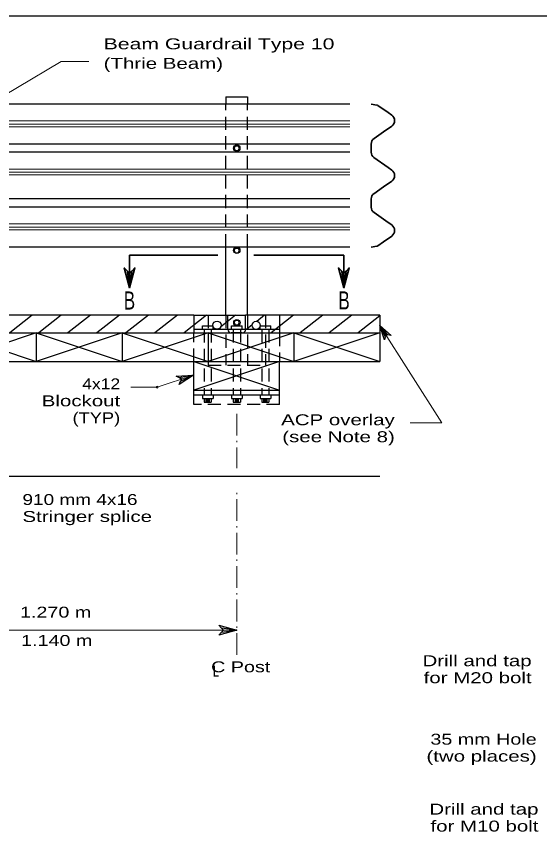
# Model space of a CAD drawing. Extents: x 13426 to 15509, y -9298 to -5111.
# Drawn here: x 15263.4 to 15326, y -5208.6 to -5111 of the extents above; entities that cross this region are included whole.
import ezdxf
from ezdxf.enums import TextEntityAlignment as Align

# ---------------------------------------------------------------- set-up
doc = ezdxf.new("R2010")
doc.units = 0
doc.header["$LTSCALE"] = 0.52
doc.header["$PDMODE"] = 32
doc.header["$PDSIZE"] = 0.26
doc.linetypes.add('DOT_DASHED', pattern=[7.7, 5, -1.2, 0.3, -1.2])
doc.linetypes.add('MEDIUM_DASHED', pattern=[4.5, 3, -1.5])
for name, color, linetype, lineweight in [('1', 7, 'Continuous', 13), ('15', 7, 'Continuous', 13), ('16', 7, 'Continuous', 25), ('2', 7, 'Continuous', 25), ('20', 7, 'Continuous', 13), ('30', 7, 'Continuous', 25), ('4', 7, 'Continuous', 13), ('5', 7, 'Continuous', 25)]:
    doc.layers.add(name, color=color, linetype=linetype, lineweight=lineweight)
doc.layers.add('19', color=7, linetype='Continuous')

msp = doc.modelspace()

# ---------------------------------------------------------------- linework, layer by layer
at = {"layer": '1', "lineweight": 25}
for p, q in [((15303.296, -5121.538), (15188.44, -5121.538)), ((15303.296, -5126.334), (15188.44, -5126.334)), ((15289.467, -5126.809), (15289.626, -5126.535)), ((15289.626, -5126.535), (15289.947, -5126.535)), ((15290.105, -5126.813), (15289.947, -5126.535)), ((15303.296, -5127.298), (15188.44, -5127.298)), ((15289.626, -5127.091), (15289.467, -5126.809)), ((15289.626, -5127.091), (15289.943, -5127.091)), ((15289.943, -5127.091), (15290.105, -5126.813)), ((15303.296, -5132.898), (15188.44, -5132.898)), ((15305.869, -5133.864), (15305.869, -5132.898)), ((15303.296, -5133.864), (15188.44, -5133.864)), ((15303.296, -5138.664), (15188.44, -5138.664)), ((15289.467, -5139.043), (15289.626, -5138.769)), ((15289.626, -5139.326), (15289.467, -5139.043)), ((15289.626, -5138.769), (15289.947, -5138.769)), ((15289.626, -5139.326), (15289.943, -5139.326)), ((15289.943, -5139.326), (15290.105, -5139.047)), ((15290.105, -5139.047), (15289.947, -5138.769)), ((15284.634, -5146.793), (15193.834, -5146.793)), ((15284.634, -5146.793), (15284.634, -5148.935)), ((15284.634, -5146.793), (15290.845, -5146.793)), ((15288.704, -5148.507), (15288.704, -5146.793)), ((15306.907, -5146.793), (15290.845, -5146.793)), ((15290.845, -5148.507), (15290.845, -5146.793)), ((15294.914, -5146.793), (15294.914, -5148.935)), ((15289.48, -5147.691), (15289.639, -5147.416)), ((15289.639, -5147.973), (15289.48, -5147.691)), ((15289.639, -5147.416), (15289.96, -5147.416)), ((15289.639, -5147.973), (15289.956, -5147.973)), ((15289.956, -5147.973), (15290.119, -5147.695)), ((15290.119, -5147.695), (15289.96, -5147.416)), ((15294.914, -5148.507), (15284.634, -5148.507)), ((15290.417, -5148.935), (15289.132, -5148.935)), ((15284.634, -5156.323), (15284.634, -5152.362)), ((15294.914, -5156.323), (15294.914, -5152.362))]:
    msp.add_line(p, q, dxfattribs=at)
at = {"layer": '1', "lineweight": 35}
for p, q in [((15305.869, -5121.538), (15306.541, -5121.657)), ((15307.879, -5122.562), (15306.672, -5121.712)), ((15308.324, -5122.867), (15307.881, -5122.56)), ((15308.324, -5124.198), (15307.35, -5124.87)), ((15307.351, -5124.87), (15306.214, -5125.671)), ((15305.869, -5127.307), (15305.869, -5126.334)), ((15307.886, -5129.129), (15306.167, -5127.94)), ((15308.324, -5129.446), (15307.881, -5129.136)), ((15307.351, -5131.443), (15306.167, -5132.27)), ((15308.324, -5130.766), (15307.352, -5131.446)), ((15305.869, -5132.898), (15305.869, -5133.864)), ((15308.324, -5137.334), (15307.351, -5138.015)), ((15307.351, -5138.013), (15306.672, -5138.495)), ((15305.871, -5138.664), (15306.543, -5138.549))]:
    msp.add_line(p, q, dxfattribs=at)
at = {"layer": '1'}
for p, q in [((15303.296, -5123.566), (15188.44, -5123.566)), ((15303.296, -5123.949), (15188.44, -5123.949)), ((15303.296, -5124.268), (15188.44, -5124.268)), ((15303.296, -5129.326), (15188.44, -5129.326)), ((15303.296, -5129.709), (15188.44, -5129.709)), ((15303.296, -5130.028), (15188.44, -5130.028)), ((15303.296, -5135.893), (15188.44, -5135.893)), ((15303.296, -5136.276), (15188.44, -5136.276)), ((15303.296, -5136.595), (15188.44, -5136.595))]:
    msp.add_line(p, q, dxfattribs=at)
at = {"layer": '1', "linetype": 'MEDIUM_DASHED', "lineweight": 25}
for p, q in [((15284.634, -5152.362), (15284.634, -5148.935)), ((15294.914, -5148.935), (15294.914, -5152.362)), ((15294.914, -5157.501), (15294.914, -5156.323))]:
    msp.add_line(p, q, dxfattribs=at)
at = {"layer": '1', "lineweight": 35}
msp.add_lwpolyline([(15308.324, -5136.012), (15307.881, -5135.705), (15306.214, -5134.537)], dxfattribs=at)
at = {"layer": '1', "linetype": 'MEDIUM_DASHED', "lineweight": 25}
msp.add_lwpolyline([(15294.914, -5157.501), (15284.634, -5157.501), (15284.634, -5156.323)], dxfattribs=at)
at = {"layer": '1', "lineweight": 25}
for centre in [(15287.4185, -5147.9974), (15292.1095, -5148.0187)]:
    msp.add_circle(centre, 0.4819, dxfattribs=at)
for centre, radius, start, end in [((15306.4821, -5121.9768), 0.3231, 55.00074, 79.99915), ((15307.8591, -5130.1024), 0.8078, 304.98394, 55.01555), ((15289.1318, -5148.5067), 0.4283, 180, 269.99999), ((15290.4167, -5148.5067), 0.4283, 270, 359.99999)]:
    msp.add_arc(centre, radius, start, end, dxfattribs=at)
at = {"layer": '1', "lineweight": 35}
for centre, radius, start, end in [((15307.8591, -5123.5327), 0.8078, 304.98447, 55.01608), ((15306.6745, -5126.3329), 0.8078, 124.98447, 180.00047), ((15306.6745, -5127.3022), 0.8078, 179.99952, 235.01552), ((15307.8591, -5130.1023), 0.8078, 304.98447, 55.01608), ((15306.6745, -5132.9025), 0.8078, 124.98453, 180.00053), ((15306.6745, -5133.8718), 0.8078, 179.99957, 235.01557), ((15307.8591, -5136.672), 0.8078, 304.98394, 55.01555), ((15306.4865, -5138.2301), 0.3231, 280.00088, 304.99929)]:
    msp.add_arc(centre, radius, start, end, dxfattribs=at)
at = {"layer": '15', "lineweight": 35}
for p, q in [((15276.957, -5139.625), (15276.957, -5143.516)), ((15276.957, -5139.625), (15287.511, -5139.625)), ((15291.823, -5139.625), (15302.595, -5139.625)), ((15302.595, -5139.625), (15302.595, -5143.516))]:
    msp.add_line(p, q, dxfattribs=at)
at = {"layer": '15'}
for p, q in [((15280.253, -5155.411), (15284.602, -5153.97)), ((15277.122, -5155.411), (15280.253, -5155.411))]:
    msp.add_line(p, q, dxfattribs=at)
for points in [[(15258.277, -5122.691), (15268.79, -5116.467), (15272.079, -5116.467)], [(15310.526, -5159.697), (15314.323, -5159.697), (15306.907, -5148.036)]]:
    msp.add_lwpolyline(points, dxfattribs=at)
msp.add_point((15280.253, -5155.411), dxfattribs=at)
at = {"layer": '16', "lineweight": 35}
for points in [[(15277.218, -5141.525), (15277.601, -5141.158), (15276.957, -5143.516), (15276.314, -5141.158), (15276.697, -5141.525), (15276.957, -5143.516), (15277.218, -5141.525), (15276.957, -5141.786), (15276.697, -5141.525)], [(15302.856, -5141.525), (15303.238, -5141.158), (15302.595, -5143.516), (15301.952, -5141.158), (15302.335, -5141.525), (15302.595, -5143.516), (15302.856, -5141.525), (15302.595, -5141.786), (15302.335, -5141.525)]]:
    msp.add_lwpolyline(points, dxfattribs=at)
at = {"layer": '16'}
for points in [[(15307.531, -5149.375), (15307.439, -5149.754), (15306.907, -5148.036), (15308.237, -5149.246), (15307.855, -5149.169), (15306.907, -5148.036), (15307.531, -5149.375), (15307.59, -5149.11), (15307.855, -5149.169)], [(15282.931, -5154.292), (15282.533, -5154.081), (15284.602, -5153.97), (15282.876, -5155.116), (15283.07, -5154.71), (15284.602, -5153.97), (15282.931, -5154.292), (15283.21, -5154.432), (15283.07, -5154.71)], [(15287.965, -5184.261), (15287.631, -5183.913), (15289.775, -5184.497), (15287.631, -5185.082), (15287.965, -5184.734), (15289.775, -5184.497), (15287.965, -5184.261), (15288.202, -5184.497), (15287.965, -5184.734)]]:
    msp.add_lwpolyline(points, dxfattribs=at)
at = {"layer": '2'}
for centre in [(15289.7842, -5126.8131), (15289.7842, -5139.0472), (15289.7974, -5147.6947)]:
    msp.add_circle(centre, 0.3814, dxfattribs=at)
at = {"layer": '30'}
msp.add_line((15509.151, -5111.044), (15181.119, -5111.044), dxfattribs=at)
at = {"layer": '4', "lineweight": 25}
for p, q in [((15265.317, -5146.793), (15262.624, -5148.935)), ((15268.791, -5146.793), (15266.099, -5148.935)), ((15272.266, -5146.793), (15269.573, -5148.935)), ((15275.74, -5146.793), (15273.048, -5148.935)), ((15279.215, -5146.793), (15276.522, -5148.935)), ((15282.689, -5146.793), (15279.997, -5148.935)), ((15286.164, -5146.793), (15283.472, -5148.935)), ((15289.638, -5146.793), (15287.846, -5148.219)), ((15293.113, -5146.793), (15292.173, -5147.541)), ((15296.588, -5146.793), (15293.895, -5148.935)), ((15300.062, -5146.793), (15297.37, -5148.935)), ((15303.537, -5146.793), (15300.844, -5148.935)), ((15306.907, -5146.876), (15304.319, -5148.935)), ((15306.907, -5146.793), (15306.907, -5152.362)), ((15291.63, -5147.973), (15290.959, -5148.507)), ((15193.834, -5148.935), (15306.907, -5148.935)), ((15255.51, -5148.935), (15265.789, -5152.362)), ((15265.789, -5148.935), (15255.51, -5152.362)), ((15265.789, -5148.935), (15265.789, -5152.362)), ((15265.789, -5148.935), (15276.069, -5152.362)), ((15276.069, -5148.935), (15265.789, -5152.362)), ((15276.069, -5148.935), (15276.069, -5152.362)), ((15276.069, -5148.935), (15286.348, -5152.362)), ((15286.348, -5148.935), (15276.069, -5152.362)), ((15286.348, -5148.935), (15286.348, -5152.362)), ((15286.348, -5148.935), (15296.627, -5152.362)), ((15296.627, -5148.935), (15286.348, -5152.362)), ((15296.627, -5148.935), (15296.627, -5152.362)), ((15296.627, -5148.935), (15306.907, -5152.362)), ((15306.907, -5148.935), (15296.627, -5152.362)), ((15193.834, -5152.362), (15306.907, -5152.362)), ((15294.914, -5152.362), (15284.634, -5155.788)), ((15284.634, -5152.362), (15294.914, -5155.788)), ((15284.634, -5155.788), (15294.914, -5155.788)), ((15284.634, -5156.323), (15294.914, -5156.323)), ((15193.834, -5166.068), (15306.907, -5166.068))]:
    msp.add_line(p, q, dxfattribs=at)
at = {"layer": '4', "linetype": 'DOT_DASHED'}
for p, q in [((15289.775, -5158.616), (15289.775, -5165.118)), ((15289.775, -5187.443), (15289.775, -5167.688))]:
    msp.add_line(p, q, dxfattribs=at)
at = {"layer": '4'}
msp.add_line((15246.944, -5184.497), (15289.775, -5184.497), dxfattribs=at)
at = {"layer": '5'}
for p, q in [((15288.49, -5120.681), (15291.059, -5120.681)), ((15288.49, -5120.681), (15288.49, -5121.538)), ((15291.059, -5120.681), (15291.059, -5121.538)), ((15288.49, -5146.793), (15288.49, -5138.664)), ((15291.059, -5146.793), (15291.059, -5138.664)), ((15285.672, -5148.506), (15285.672, -5148.078)), ((15285.672, -5148.078), (15286.957, -5148.078)), ((15286.957, -5148.506), (15286.957, -5148.078)), ((15289.155, -5148.506), (15289.155, -5148.078)), ((15289.155, -5148.078), (15290.44, -5148.078)), ((15290.44, -5148.506), (15290.44, -5148.078)), ((15292.581, -5148.506), (15292.581, -5148.078)), ((15292.581, -5148.078), (15293.866, -5148.078)), ((15293.866, -5148.506), (15293.866, -5148.078)), ((15285.672, -5156.324), (15285.672, -5156.753)), ((15285.672, -5156.753), (15286.957, -5156.753)), ((15285.873, -5156.753), (15285.873, -5157.224)), ((15286.05, -5156.903), (15286.549, -5156.903)), ((15286.729, -5156.753), (15286.729, -5157.224)), ((15286.957, -5156.324), (15286.957, -5156.753)), ((15289.155, -5156.324), (15289.155, -5156.753)), ((15289.155, -5156.753), (15290.44, -5156.753)), ((15289.356, -5156.753), (15289.356, -5157.224)), ((15289.533, -5156.904), (15290.032, -5156.904)), ((15290.212, -5156.753), (15290.212, -5157.224)), ((15290.44, -5156.324), (15290.44, -5156.753)), ((15292.581, -5156.324), (15292.581, -5156.753)), ((15292.581, -5156.753), (15293.866, -5156.753)), ((15292.782, -5156.753), (15292.782, -5157.224)), ((15292.959, -5156.903), (15293.458, -5156.903)), ((15293.639, -5156.753), (15293.639, -5157.224)), ((15293.866, -5156.324), (15293.866, -5156.753)), ((15285.873, -5157.224), (15286.729, -5157.224)), ((15286.05, -5157.037), (15286.549, -5157.037)), ((15289.356, -5157.224), (15290.212, -5157.224)), ((15289.533, -5157.037), (15290.032, -5157.037)), ((15292.782, -5157.224), (15293.639, -5157.224)), ((15292.959, -5157.037), (15293.458, -5157.037))]:
    msp.add_line(p, q, dxfattribs=at)
at = {"layer": '5', "linetype": 'MEDIUM_DASHED'}
for p, q in [((15288.49, -5138.664), (15288.49, -5121.538)), ((15291.059, -5138.664), (15291.059, -5121.538)), ((15286.348, -5146.793), (15286.348, -5152.79)), ((15288.49, -5146.793), (15288.49, -5152.79)), ((15291.059, -5146.793), (15291.059, -5152.79)), ((15293.201, -5146.793), (15293.201, -5152.79)), ((15285.873, -5148.507), (15285.873, -5156.323)), ((15286.729, -5148.507), (15286.729, -5156.323)), ((15289.356, -5148.506), (15289.356, -5156.323)), ((15290.212, -5148.506), (15290.212, -5156.323)), ((15292.782, -5148.507), (15292.782, -5156.323)), ((15293.639, -5148.507), (15293.639, -5156.323)), ((15286.348, -5152.79), (15293.201, -5152.79))]:
    msp.add_line(p, q, dxfattribs=at)

# ---------------------------------------------------------------- texts
at = {"layer": '19'}
for s, width, p in [('910 mm 4x16', 1.3, (15264.141, -5169.515)), ('Stringer splice', 1.4, (15264.141, -5171.543))]:
    msp.add_text(s, height=1.307, dxfattribs=dict(at, width=width)).set_placement(p)
at = {"layer": '19', "width": 1.35}
for s, p in [('1.270 m', (15268.1095, -5182.989)), ('1.140 m', (15268.2405, -5186.381))]:
    msp.add_text(s, height=1.307, dxfattribs=at).set_placement(p, align=Align.CENTER)
at = {"layer": '19'}
for s, width, p in [('Drill and tap', 1.4, (15325.063, -5188.805)), ('for M20 bolt', 1.4, (15325.063, -5190.833)), ('35 mm Hole', 1.35, (15325.666, -5198.19)), ('(two places)', 1.4, (15325.666, -5200.218)), ('Drill and tap', 1.4, (15325.883, -5206.557)), ('for M10 bolt', 1.4, (15325.883, -5208.585))]:
    msp.add_text(s, height=1.307, dxfattribs=dict(at, width=width)).set_placement(p, align=Align.RIGHT)
at = {"layer": '20'}
for s, width, p in [('Beam Guardrail Type 10', 1.45, (15273.859, -5114.99)), ('(Thrie Beam)', 1.4, (15273.859, -5117.327))]:
    msp.add_text(s, height=1.307, dxfattribs=dict(at, width=width)).set_placement(p)
for s, height, width, p in [('B', 2.163, 0.7, (15276.945, -5146.129)), ('B', 2.163, 0.7, (15302.622, -5146.119)), ('C Post', 1.307, 1.35, (15290.252, -5189.532)), ('L', 1.307, 0.75, (15287.294, -5190.059))]:
    msp.add_text(s, height=height, dxfattribs=dict(at, width=width)).set_placement(p, align=Align.CENTER)
for s, width, p in [('4x12', 1.2, (15275.835, -5155.678)), ('Blockout', 1.4, (15275.836, -5157.706)), ('(TYP)', 1.25, (15275.836, -5159.734)), ('ACP overlay', 1.4, (15308.691, -5159.972)), ('(see Note 8)', 1.4, (15308.691, -5162))]:
    msp.add_text(s, height=1.307, dxfattribs=dict(at, width=width)).set_placement(p, align=Align.RIGHT)

doc.saveas('drawing.dxf')
